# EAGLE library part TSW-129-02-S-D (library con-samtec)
THROUGH-HOLE .025" SQ POST HEADER Source: Samtec TSW.pdf
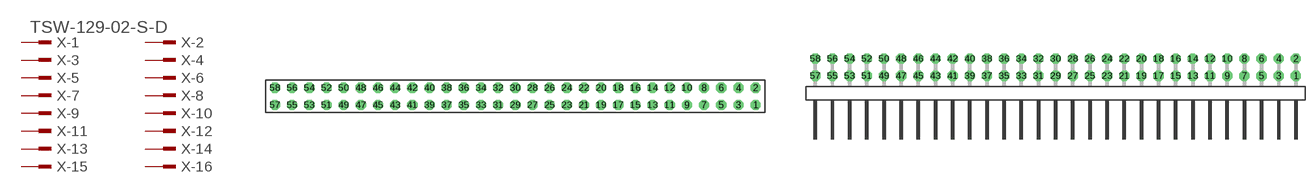
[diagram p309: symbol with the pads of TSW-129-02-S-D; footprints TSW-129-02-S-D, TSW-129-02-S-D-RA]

Designator prefix X; gates -1=MPINV -2=MPIN -3=MPIN -4=MPIN -5=MPIN -6=MPIN -7=MPIN -8=MPIN -9=MPIN -10=MPIN -11=MPIN -12=MPIN -13=MPIN -14=MPIN -15=MPIN -16=MPIN -17=MPIN -18=MPIN -19=MPIN -20=MPIN -21=MPIN -22=MPIN -23=MPIN -24=MPIN -25=MPIN -26=MPIN -27=MPIN -28=MPIN -29=MPIN -30=MPIN -31=MPIN -32=MPIN -33=MPIN -34=MPIN -35=MPIN -36=MPIN -37=MPIN -38=MPIN -39=MPIN -40=MPIN -41=MPIN -42=MPIN -43=MPIN -44=MPIN -45=MPIN -46=MPIN -47=MPIN -48=MPIN -49=MPIN -50=MPIN -51=MPIN -52=MPIN -53=MPIN -54=MPIN -55=MPIN -56=MPIN -57=MPIN -58=MPIN

## TSW-129-02-S-D (OC_FARNELL: unknown; OC_NEWARK: unknown)  [TSW-129-02-S-D]
1  -1:1  pas
2  -2:1  pas
3  -3:1  pas
4  -4:1  pas
5  -5:1  pas
6  -6:1  pas
7  -7:1  pas
8  -8:1  pas
9  -9:1  pas
10  -10:1  pas
11  -11:1  pas
12  -12:1  pas
13  -13:1  pas
14  -14:1  pas
15  -15:1  pas
16  -16:1  pas
17  -17:1  pas
18  -18:1  pas
19  -19:1  pas
20  -20:1  pas
21  -21:1  pas
22  -22:1  pas
23  -23:1  pas
24  -24:1  pas
25  -25:1  pas
26  -26:1  pas
27  -27:1  pas
28  -28:1  pas
29  -29:1  pas
30  -30:1  pas
31  -31:1  pas
32  -32:1  pas
33  -33:1  pas
34  -34:1  pas
35  -35:1  pas
36  -36:1  pas
37  -37:1  pas
38  -38:1  pas
39  -39:1  pas
40  -40:1  pas
41  -41:1  pas
42  -42:1  pas
43  -43:1  pas
44  -44:1  pas
45  -45:1  pas
46  -46:1  pas
47  -47:1  pas
48  -48:1  pas
49  -49:1  pas
50  -50:1  pas
51  -51:1  pas
52  -52:1  pas
53  -53:1  pas
54  -54:1  pas
55  -55:1  pas
56  -56:1  pas
57  -57:1  pas
58  -58:1  pas

## TSW-129-02-S-D-RA (OC_FARNELL: unknown; OC_NEWARK: unknown)  [TSW-129-02-S-D-RA]
Pads as for TSW-129-02-S-D

## Footprint TSW-129-02-S-D (pad centres in mm)
THROUGH-HOLE .025" SQ POST HEADER Source: Samtec TSW.pdf
drill 1 pad 1.5 octagon: 1 35.56,-1.27; 2 35.56,1.27; 3 33.02,-1.27; 4 33.02,1.27; 5 30.48,-1.27; 6 30.48,1.27; 7 27.94,-1.27; 8 27.94,1.27; 9 25.4,-1.27; 10 25.4,1.27; 11 22.86,-1.27; 12 22.86,1.27; 13 20.32,-1.27; 14 20.32,1.27; 15 17.78,-1.27; 16 17.78,1.27; 17 15.24,-1.27; 18 15.24,1.27; 19 12.7,-1.27; 20 12.7,1.27; 21 10.16,-1.27; 22 10.16,1.27; 23 7.62,-1.27; 24 7.62,1.27; 25 5.08,-1.27; 26 5.08,1.27; 27 2.54,-1.27; 28 2.54,1.27; 29 0,-1.27; 30 0,1.27; 31 -2.54,-1.27; 32 -2.54,1.27; 33 -5.08,-1.27; 34 -5.08,1.27; 35 -7.62,-1.27; 36 -7.62,1.27; 37 -10.16,-1.27; 38 -10.16,1.27; 39 -12.7,-1.27; 40 -12.7,1.27; 41 -15.24,-1.27; 42 -15.24,1.27; 43 -17.78,-1.27; 44 -17.78,1.27; 45 -20.32,-1.27; 46 -20.32,1.27; 47 -22.86,-1.27; 48 -22.86,1.27; 49 -25.4,-1.27; 50 -25.4,1.27; 51 -27.94,-1.27; 52 -27.94,1.27; 53 -30.48,-1.27; 54 -30.48,1.27; 55 -33.02,-1.27; 56 -33.02,1.27; 57 -35.56,-1.27; 58 -35.56,1.27

## Footprint TSW-129-02-S-D-RA (pad centres in mm)
THROUGH-HOLE .025" SQ POST HEADER Source: Samtec TSW.pdf
drill 1 pad 1.5 octagon: 1 35.56,1.524; 2 35.56,4.064; 3 33.02,1.524; 4 33.02,4.064; 5 30.48,1.524; 6 30.48,4.064; 7 27.94,1.524; 8 27.94,4.064; 9 25.4,1.524; 10 25.4,4.064; 11 22.86,1.524; 12 22.86,4.064; 13 20.32,1.524; 14 20.32,4.064; 15 17.78,1.524; 16 17.78,4.064; 17 15.24,1.524; 18 15.24,4.064; 19 12.7,1.524; 20 12.7,4.064; 21 10.16,1.524; 22 10.16,4.064; 23 7.62,1.524; 24 7.62,4.064; 25 5.08,1.524; 26 5.08,4.064; 27 2.54,1.524; 28 2.54,4.064; 29 0,1.524; 30 0,4.064; 31 -2.54,1.524; 32 -2.54,4.064; 33 -5.08,1.524; 34 -5.08,4.064; 35 -7.62,1.524; 36 -7.62,4.064; 37 -10.16,1.524; 38 -10.16,4.064; 39 -12.7,1.524; 40 -12.7,4.064; 41 -15.24,1.524; 42 -15.24,4.064; 43 -17.78,1.524; 44 -17.78,4.064; 45 -20.32,1.524; 46 -20.32,4.064; 47 -22.86,1.524; 48 -22.86,4.064; 49 -25.4,1.524; 50 -25.4,4.064; 51 -27.94,1.524; 52 -27.94,4.064; 53 -30.48,1.524; 54 -30.48,4.064; 55 -33.02,1.524; 56 -33.02,4.064; 57 -35.56,1.524; 58 -35.56,4.064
